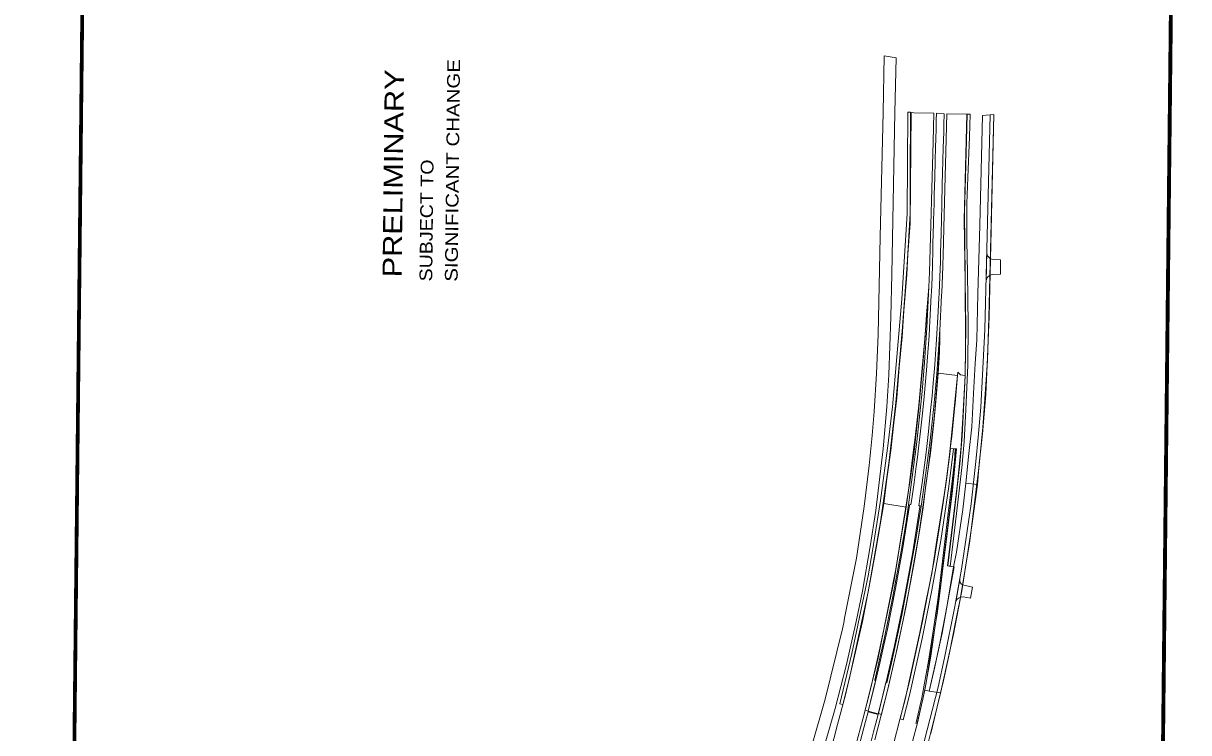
# Model space of a CAD drawing. Extents: x 2356576 to 2377878, y 6966390 to 6990634.
# Drawn here: x 2363518 to 2367164, y 6983363 to 6985583 of the extents above; entities that cross this region are included whole.
import ezdxf

# ---------------------------------------------------------------- set-up
doc = ezdxf.new("R2010")
doc.units = 0
doc.header["$LTSCALE"] = 7.1
for name, color, linetype, lineweight in [('10', 7, 'Continuous', 13), ('11', 7, 'Continuous', 13), ('14', 7, 'Continuous', 13), ('19', 7, 'Continuous', 13), ('8', 7, 'Continuous', 13), ('9', 7, 'Continuous', 13)]:
    doc.layers.add(name, color=color, linetype=linetype, lineweight=lineweight)
doc.layers.add('5', color=7, linetype='Continuous')

msp = doc.modelspace()

# ---------------------------------------------------------------- linework, layer by layer
at = {"layer": '10'}
for points in [[(2366284.777, 6985305.032), (2366282.681, 6984988.24), (2366265.755, 6984719.809), (2366236.588, 6984382.82), (2366224.006, 6984269.534), (2366199.751, 6984089.55), (2366174.68, 6983932.781), (2366160.556, 6983854.588), (2366124.896, 6983679.561), (2366109.858, 6983610.682), (2366072.368, 6983453.913), (2366081.992, 6983451.723), (2366101.396, 6983529.905), (2366161.167, 6983804.531), (2366199.691, 6984023.088), (2366225.762, 6984206.278), (2366247.83, 6984396.609), (2366267.791, 6984619.793), (2366282.736, 6984827.838), (2366292.325, 6984988.317), (2366292.546, 6985105.335), (2366293.842, 6985304.74)], [(2366210.738, 6984087.463), (2366209.594, 6984081.031), (2366279.625, 6984069.509), (2366280.675, 6984075.907), (2366287.94, 6984129.049), (2366292.598, 6984163.299), (2366302.896, 6984248.239), (2366308.318, 6984287.44), (2366318.992, 6984388.599), (2366327.169, 6984469.673), (2366333.322, 6984538.798), (2366339.115, 6984607.303), (2366343.748, 6984670.767), (2366350.293, 6984758.585), (2366353.184, 6984804.101), (2366355.182, 6984877.017), (2366357.322, 6984951.672), (2366360.174, 6985066.598), (2366364.168, 6985212.697), (2366366.448, 6985302.079), (2366303.673, 6985303.227), (2366295.223, 6985303.654), (2366291.857, 6984956.932), (2366285.352, 6984860.858), (2366281.558, 6984795.792), (2366272.884, 6984683.959), (2366266.921, 6984601.61), (2366257.705, 6984506.551), (2366250.116, 6984411.494), (2366241.443, 6984333.211), (2366232.227, 6984246.796), (2366219.596, 6984157.406), (2366216.037, 6984131.86)], [(2366406.626, 6985300.239), (2366469.865, 6985298.851), (2366460.982, 6984968.629), (2366464.235, 6984775.466), (2366466.403, 6984634.151), (2366464.099, 6984481.485), (2366450.136, 6984483.026), (2366441.695, 6984491.613), (2366440.702, 6984481.299), (2366380.161, 6984488.441), (2366383.825, 6984554.336), (2366384.908, 6984596.669), (2366385.373, 6984621.935), (2366390.692, 6984732.018), (2366391.043, 6984741.05), (2366394.347, 6984820.823), (2366394.417, 6984827.218), (2366395.472, 6984857.018), (2366398.706, 6984984.59)], [(2366409.787, 6983885.123), (2366422.738, 6983988.994), (2366432.36, 6984067.012), (2366447.624, 6984204.582), (2366454.635, 6984291.316), (2366464.45, 6984481.409), (2366465.92, 6984567.931), (2366464.698, 6984792.94), (2366461.834, 6984993.126), (2366463.929, 6985064.628), (2366468.12, 6985216.295), (2366470.231, 6985299.024), (2366479.705, 6985298.68), (2366477.938, 6985228.157), (2366472.808, 6985100.647), (2366470.056, 6985019.565), (2366469.506, 6984901.043), (2366471.941, 6984803.846), (2366473.917, 6984639.818), (2366472.697, 6984512.959), (2366466.552, 6984373.353), (2366460.811, 6984274.892), (2366454.135, 6984192.083), (2366437.213, 6984049.204), (2366417.647, 6983883.848)], [(2366351.112, 6984758.825), (2366331.734, 6984515.927), (2366318.979, 6984379.755), (2366304.504, 6984243.185), (2366291.837, 6984153.402), (2366247.406, 6983874.99), (2366228.172, 6983774.514), (2366192.225, 6983597.764), (2366151.612, 6983433.44), (2366161.331, 6983431.084), (2366184.351, 6983525.221), (2366181.38, 6983527.605), (2366211.984, 6983661.365), (2366237.816, 6983789.78), (2366264.222, 6983931.028), (2366278.668, 6984017.238), (2366287.11, 6984076.102), (2366313.608, 6984273.196), (2366329.368, 6984431.201), (2366337.276, 6984522.182), (2366344.864, 6984630.04)], [(2366192.815, 6983423.026), (2366216.627, 6983520.156), (2366219.336, 6983519.609), (2366233.82, 6983581.616), (2366266.305, 6983731.414), (2366311.128, 6983974.025), (2366319.363, 6984028.459), (2366326.99, 6984070.836), (2366344.806, 6984199.04), (2366354.444, 6984278.935), (2366366.013, 6984383.902), (2366375.407, 6984485.086), (2366385.155, 6984625.23), (2366383.97, 6984571.866), (2366380.304, 6984497.106), (2366368.663, 6984356.451), (2366348.312, 6984189.001), (2366333.494, 6984076.259), (2366318.397, 6983976.598), (2366279.303, 6983760.75), (2366251.151, 6983626.862), (2366221.133, 6983494.887), (2366202.482, 6983420.583)], [(2366261.32, 6983406.605), (2366291.019, 6983528.766), (2366329.613, 6983707.039), (2366367.511, 6983901.856), (2366395.449, 6984083.105), (2366405.529, 6984154.134), (2366418.167, 6984252.441), (2366428.11, 6984251.318), (2366412.786, 6984133.915), (2366388.171, 6983964.899), (2366360.255, 6983809.41), (2366329.827, 6983658.367), (2366290.886, 6983484.867), (2366270.842, 6983403.918)], [(2366311.532, 6983394.897), (2366329.146, 6983471.968), (2366350.077, 6983586.812), (2366364.327, 6983680.862), (2366378.52, 6983779.011), (2366389.358, 6983864.824), (2366411.042, 6984049.849), (2366424.339, 6984158.827), (2366430.749, 6984212.643), (2366432.762, 6984250.949), (2366436.16, 6984251.427), (2366428.737, 6984174.822), (2366422.802, 6984115.671), (2366409.986, 6984009.98), (2366396.205, 6983899.048), (2366387.822, 6983828.263), (2366372.59, 6983711.207), (2366358.844, 6983626.854), (2366342.19, 6983518.924), (2366332.094, 6983468.363), (2366328.182, 6983450.386), (2366325.024, 6983436.731), (2366314.17, 6983392.31), (2366310.403, 6983393.289)]]:
    msp.add_lwpolyline(points, close=True, dxfattribs=at)
for points in [[(2366181.732, 6983341.196), (2366222.411, 6983499.019), (2366246.012, 6983604.274), (2366270.339, 6983715.457), (2366293.614, 6983832.98), (2366306.976, 6983907.353), (2366321.129, 6983993.588), (2366332.631, 6984068.365), (2366341.211, 6984138.451), (2366355.443, 6984237.978), (2366363.918, 6984313.889), (2366368.16, 6984355.367), (2366370.859, 6984376.864), (2366375.103, 6984425.159), (2366380.161, 6984488.441), (2366440.702, 6984481.299), (2366436.186, 6984431.33), (2366432.799, 6984394.7), (2366430.993, 6984376.281), (2366426.026, 6984322.5), (2366422.187, 6984289.682), (2366417.835, 6984253.165), (2366415.189, 6984232.949), (2366405.706, 6984157.995), (2366400.059, 6984113.523), (2366387.571, 6984035.453), (2366376.238, 6983965.41), (2366364.16, 6983889.724), (2366359.644, 6983861.563), (2366343.188, 6983781.781), (2366322.233, 6983677.157), (2366296.492, 6983557.417), (2366276.358, 6983467.291), (2366259.822, 6983404.165), (2366240.493, 6983327.22)], [(2366043.047, 6983303.01), (2366065.147, 6983388.728), (2366090.145, 6983481.46), (2366118.281, 6983602.905), (2366143.451, 6983711.137), (2366167.415, 6983837.702), (2366185.997, 6983940.705), (2366209.594, 6984081.031), (2366279.625, 6984069.509), (2366258.841, 6983945.198), (2366242.176, 6983841.099), (2366216.865, 6983720.186), (2366194.53, 6983613.332), (2366169.345, 6983503.692), (2366144.285, 6983405.323), (2366114.886, 6983297.139)]]:
    msp.add_lwpolyline(points, dxfattribs=at)
at = {"layer": '11'}
msp.add_lwpolyline([(2366429.523, 6983881.883), (2366402.306, 6983729.15), (2366386.219, 6983648.626), (2366369.206, 6983569.393), (2366351.748, 6983493.284), (2366338.206, 6983496.031), (2366339.467, 6983502.479), (2366356.575, 6983602.727), (2366372.052, 6983706.236), (2366376.801, 6983734.906), (2366385.303, 6983800.075), (2366392.64, 6983860.164), (2366424.409, 6984121.511), (2366437.241, 6984251.233), (2366417.835, 6984253.165), (2366441.695, 6984491.612), (2366450.136, 6984483.026), (2366464.099, 6984481.485), (2366456.179, 6984330.552), (2366451.886, 6984259.727), (2366447.813, 6984215.716), (2366443.74, 6984175.779), (2366440.481, 6984143.993), (2366409.492, 6983885.047)], close=True, dxfattribs=at)
at = {"layer": '14'}
for points in [[(2366241.942, 6983630.483), (2366221.539, 6983540.24), (2366203.861, 6983467.211), (2366192.737, 6983422.715), (2366161.331, 6983431.084), (2366183.051, 6983518.829), (2366197.9, 6983581.291), (2366210.213, 6983637.526), (2366221.064, 6983687.338), (2366246.571, 6983814.556), (2366268.695, 6983935.389), (2366290.598, 6984074.651), (2366290.544, 6984074.292), (2366291.002, 6984077.575), (2366294.894, 6984077.084), (2366297.588, 6984094.914), (2366304.775, 6984145.95), (2366311.437, 6984196.006), (2366315.254, 6984225.069), (2366318.697, 6984253.571), (2366324.91, 6984306.642), (2366331.872, 6984372.982), (2366336.136, 6984415.237), (2366343.448, 6984498.042), (2366345.698, 6984525.468), (2366351.409, 6984606.188), (2366354.178, 6984652.453), (2366355.227, 6984670.357), (2366358.493, 6984733.6), (2366358.774, 6984741.841), (2366360.643, 6984788.712), (2366361.937, 6984827.548), (2366362.148, 6984833.943), (2366362.921, 6984864.864), (2366363.695, 6984894.927), (2366364.539, 6984923.606), (2366365.593, 6984957.559), (2366365.804, 6984968.635), (2366367.139, 6985018.478), (2366367.28, 6985028.103), (2366367.772, 6985047.816), (2366369.038, 6985099.964), (2366370.513, 6985153.827), (2366371.639, 6985195.625), (2366372.343, 6985221.996), (2366373.187, 6985252.851), (2366373.961, 6985280.277), (2366374.445, 6985301.869), (2366398.629, 6985300.443), (2366397.723, 6985266.301), (2366397.16, 6985242.434), (2366395.894, 6985193.845), (2366393.925, 6985114.798), (2366392.94, 6985079.857), (2366392.448, 6985058.958), (2366391.886, 6985036.805), (2366390.973, 6984999.49), (2366390.34, 6984982.613), (2366390.269, 6984971.075), (2366388.934, 6984923.87), (2366387.604, 6984866.946), (2366387.546, 6984863.002), (2366386.797, 6984835.174), (2366386.105, 6984814.965), (2366383.159, 6984738.817), (2366383.07, 6984736.758), (2366382.531, 6984724.131), (2366380.378, 6984681.66), (2366374.989, 6984593.482), (2366371.921, 6984548.204), (2366369.225, 6984514.365), (2366364.584, 6984457.572), (2366360.841, 6984416.998), (2366356.275, 6984371.578), (2366349.312, 6984305.8), (2366343.999, 6984259.115), (2366340.855, 6984231.667), (2366334.718, 6984184.353), (2366329.402, 6984144.968), (2366322.665, 6984096.599), (2366319.222, 6984073.644), (2366323.115, 6984072.872), (2366322.708, 6984069.597), (2366314.463, 6984015.814), (2366299.272, 6983922.524), (2366285.442, 6983843.35), (2366272.038, 6983775.412), (2366254.526, 6983690.178)], [(2366130.668, 6983314.946), (2366142.286, 6983358.217), (2366152.987, 6983398.495), (2366160.563, 6983428.067), (2366192.06, 6983420.054), (2366177.98, 6983366.325), (2366163.706, 6983312.115), (2366161.408, 6983307.125)]]:
    msp.add_lwpolyline(points, close=True, dxfattribs=at)
at = {"layer": '19', "lineweight": 40}
msp.add_lwpolyline([(2363758.773, 6990629.355), (2367158.576, 6990592.767), (2366922.891, 6968646.236), (2363523.088, 6968682.826)], close=True, dxfattribs=at)
at = {"layer": '8', "lineweight": 40}
for points in [[(2363753.827, 6990634.409), (2367163.63, 6990597.713), (2366927.837, 6968641.182), (2363518.034, 6968677.88)], [(2363758.773, 6990629.355), (2367158.576, 6990592.767), (2366922.891, 6968646.236), (2363523.088, 6968682.826)]]:
    msp.add_lwpolyline(points, close=True, dxfattribs=at)
at = {"layer": '9'}
for p, q in [((2366531.968, 6984868.702), (2366529.832, 6984772.718)), ((2366447.696, 6983844.091), (2366435.218, 6983773.016))]:
    msp.add_line(p, q, dxfattribs=at)
for points in [[(2365984.145, 6983319.504), (2366026.683, 6983467.804), (2366080.29, 6983688.621), (2366084.404, 6983707.573), (2366087.423, 6983721.721), (2366124.108, 6983909.842), (2366147.987, 6984071.532), (2366163.875, 6984199.635), (2366173.463, 6984293.665), (2366179.783, 6984368.733), (2366187.404, 6984486.878), (2366192.305, 6984608.939), (2366198.895, 6984914.637), (2366207.462, 6985304.047), (2366210.921, 6985481.626), (2366248.866, 6985475.047), (2366244.413, 6985304.597), (2366234.871, 6984797.943), (2366231.598, 6984664.674), (2366229.191, 6984572.78), (2366225.236, 6984482.692), (2366218.968, 6984383.164), (2366207.587, 6984251.399), (2366184.526, 6984058.361), (2366167.62, 6983946.313), (2366142.79, 6983806.186), (2366123.538, 6983710.911), (2366093.106, 6983576.667), (2366057.831, 6983439.075), (2366024.809, 6983323.056)], [(2366328.211, 6983303.549), (2366380.158, 6983505.924), (2366400.117, 6983597.705), (2366432.197, 6983758.247), (2366452.853, 6983875.034), (2366483.056, 6984079.526), (2366498.048, 6984212.321), (2366505.566, 6984287.035), (2366513.411, 6984381.758), (2366525.932, 6984624.746), (2366542.277, 6985297.149), (2366554.351, 6985298.132), (2366538.749, 6984662.482), (2366534.135, 6984527.78), (2366519.99, 6984318.451), (2366508.366, 6984200.517), (2366478.763, 6983963.252), (2366448.621, 6983779.623), (2366427.64, 6983671.819), (2366386.09, 6983481.738), (2366346.323, 6983323.551)], [(2366550.397, 6984797.535), (2366574.63, 6984798.103), (2366574.714, 6984842.733), (2366552.438, 6984843.808)], [(2366457.973, 6983788.324), (2366481.217, 6983784.295), (2366487.158, 6983818.893), (2366456.506, 6983826.087)], [(2366299.856, 6983335.931), (2366315.093, 6983394.652), (2366328.153, 6983450.43), (2366338.097, 6983496.09), (2366351.748, 6983493.284), (2366387.461, 6983487.86), (2366356.587, 6983360.535)]]:
    msp.add_lwpolyline(points, dxfattribs=at)
for points in [[(2366502.731, 6984139.713), (2366507.845, 6984204.781), (2366518.614, 6984299.063), (2366529.384, 6984421.63), (2366533.423, 6984514.565), (2366539.046, 6984665.135), (2366554.427, 6985298.354), (2366518.337, 6985295.092), (2366510.537, 6984951.503), (2366503.806, 6984736.812), (2366501.114, 6984592.696), (2366495.729, 6984518.617), (2366490.344, 6984424.335), (2366484.959, 6984320.625), (2366475.798, 6984236.58), (2366466.917, 6984143.924)], [(2366351.748, 6983493.284), (2366387.461, 6983487.86), (2366396.38, 6983526.88), (2366415.227, 6983613.081), (2366435.42, 6983714.097), (2366453.596, 6983807.369), (2366468.983, 6983901.258), (2366485.23, 6984010.412), (2366502.731, 6984139.713), (2366466.317, 6984143.965), (2366456.96, 6984061.594), (2366436.766, 6983928.252), (2366427.549, 6983882.207), (2366408.496, 6983762.585), (2366392.341, 6983675.038), (2366374.84, 6983594.225)]]:
    msp.add_lwpolyline(points, close=True, dxfattribs=at)
for centre, radius, start, end in [((2366554.746, 6984866.569), 22.878, 174.65022, 264.21095), ((2366552.618, 6984774.765), 22.878, 95.57232, 185.13305), ((2366462.635, 6983840.244), 15.427, 165.55897, 246.5892), ((2366455.779, 6983767.018), 21.418, 84.11911, 163.73748)]:
    msp.add_arc(centre, radius, start, end, dxfattribs=at)

# ---------------------------------------------------------------- texts
at = {"layer": '5'}
for s, height, width, p in [('PRELIMINARY', 59.8, 1.2, (2364701.577, 6984788.018)), ('SIGNIFICANT CHANGE', 39.87, 1.2, (2364876.634, 6984774.472)), ('SUBJECT TO', 39.87, 1.15, (2364797.115, 6984775.355))]:
    msp.add_text(s, height=height, rotation=89.364, dxfattribs=dict(at, width=width)).set_placement(p)

doc.saveas('drawing.dxf')
